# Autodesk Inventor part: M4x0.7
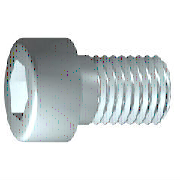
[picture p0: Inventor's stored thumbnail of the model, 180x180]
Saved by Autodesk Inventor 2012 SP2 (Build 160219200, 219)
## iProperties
Created: 2009-02
Part Number: M4x0.7
Material: 강, 연강
Description: 6각머리 태핑 나사
Document SubType Name: Modeling
Standard: KS B 1003
Standards Organization: KS
Language: ko-KR
Size Designation: M 4 x 12
Categories: <MemberInstance><Categories><Category DisplayName="조임쇠" InternalName="e4da775c-781d-43d5-af7c-5136215cf5a6" Mnemonic="FSTN"><Category DisplayName="볼트" InternalN
Density: 1 g/cm^3
Checked By: KYOUNG IL JANG
Vendor: CBT Solutions
Designer: KYOUNG IL JANG
Manager: KYOUNG IL JANG
Company: 한국ATC센터
IsCustomPart: 0
Author: KYOUNG IL JANG
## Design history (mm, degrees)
workplane "Work Plane1"
fillet "Fillet2" dims "d30" = 0.1 (= R)
revolve "본체" stored, may be unused: angle "d10" = 90 deg
sketch "스케치2"
  geometry: L1 (0, -4.9)-(0, 4.9) reference; L2 (-4.9, 0)-(4.9, 0) reference; L3 (1.732, 0)-(0.866, -1.5); L4 (0.866, -1.5)-(-0.866, -1.5); L5 (-0.866, -1.5)-(-1.732, 0); L6 (-1.732, 0)-(-0.866, 1.5); L7 (-0.866, 1.5)-(0.866, 1.5); L8 (0.866, 1.5)-(1.732, 0); 2 further points
  constraints: 12 end point, 1 coincident, 1 horizontal alignment, 1 point on line, 12 other
extrude "슬롯" join sketch "스케치2" stored distance "d11" = 10; taper "d12" = 0 deg
body "Solid1"
fillet "모깎기1" dims "d17" = 0.4 (= RR)
feature "스레드" dims "d13" = 10.25 (= GEL), "d14" = 0
chamfer "모따기1" distance "d15" = 0.42941 (= -0.5 x SPD + 0.5 x GD); stored, may be unused: second distance "d16" = 0.42941 (= GUL), angle "d27" = 45 deg
sketch "스케치1"
  geometry: L1 (-1, 0)-(12, 0); L2 (12, 0)-(12, 2); L3 (12, 2)-(1.75, 2); L4 (1.75, 2)-(1.32, 2); L5 (1.32, 2)-(0, 2); L6 (0, 2)-(0, 3.5); L7 (0, 3.5)-(-4, 3.5); L8 (-4, 3.5)-(-4, 1.732); L9 (-4, 1.732)-(-2, 1.732); L10 (-2, 1.732)-(-1, 0); L11 (-7.2, 0)-(15.2, 0) reference; L12 (0, -0.7)-(0, 4.2) reference; L13 (1.75, 2)-(0, 2)
  constraints: 22 end point, 6 parallel, 2 collinear, 2 perpendicular, 1 horizontal, 1 point on line
  dimensions: "d1" = 10.25 distance from line of L3.end L2 (= GEL); "d2" = 0.42952 distance of L4.end L3.end (computed from GAL); "d3" = 4 distance between parallel lines of L8 L6 (= KOH); "d4" = 2 distance of L8.end L9.end (= INTI); "d5" = 60 deg angle of L10 L1; "d6" = 4 diameter of L3 L1 (= GD); "d7" = 4 diameter of L5 L1 (= BDM); "d8" = 3.4641 diameter of L9 L1 (= 1.1547 x SW); "d9" = 7 diameter of L7 L1 (= KOD); "d26" = 12 distance between parallel lines of L12 L2 (= NLG)
other parameters: "GD" = 4 (= NND) [user parameter; used in 2 equation terms], "NLG" = 12 [user parameter; used in 1 equation term], "GEL" = 10.25 [user parameter; used in 2 equation terms], "KOD" = 7 [user parameter; used in 1 equation term], "KOH" = 4 [user parameter; used in 1 equation term], "INTI" = 2 [user parameter; used in 1 equation term], "GAL" = 0.42941 (= 0.61345 x PTC) [user parameter; used in 1 equation term], "GUL" = 0.42941 (= 0.61345 x PTC) [user parameter; used in 1 equation term], "BDM" = 4 (= NND) [user parameter; used in 1 equation term], "SW" = 3 [user parameter; used in 2 equation terms], "RR" = 0.4 [user parameter; used in 1 equation term], "SPD" = 3.14117 (= NND - 1.2269 x PTC) [user parameter; used in 1 equation term], "d19" = 0, "d28" = 0, "d29" = 0, "R" = 0.1 [user parameter; used in 1 equation term], "PHH" = 0.2 [user parameter], "GD1" = 3.14117 (= THREADDIA - 1.2269 x PTC) [user parameter], "THREADDIA" = 4 [user parameter; used in 1 equation term], "FAWI" = 45 deg [user parameter], "TPU" = 14.28571 (computed from PTC) [user parameter], "PTC" = 0.7 [user parameter; used in 5 equation terms], "NND" = 4 [user parameter; used in 3 equation terms], "TOA" = 30 deg [user parameter], "E0" = 3.465 (= 1.155 x SW) [user parameter]
